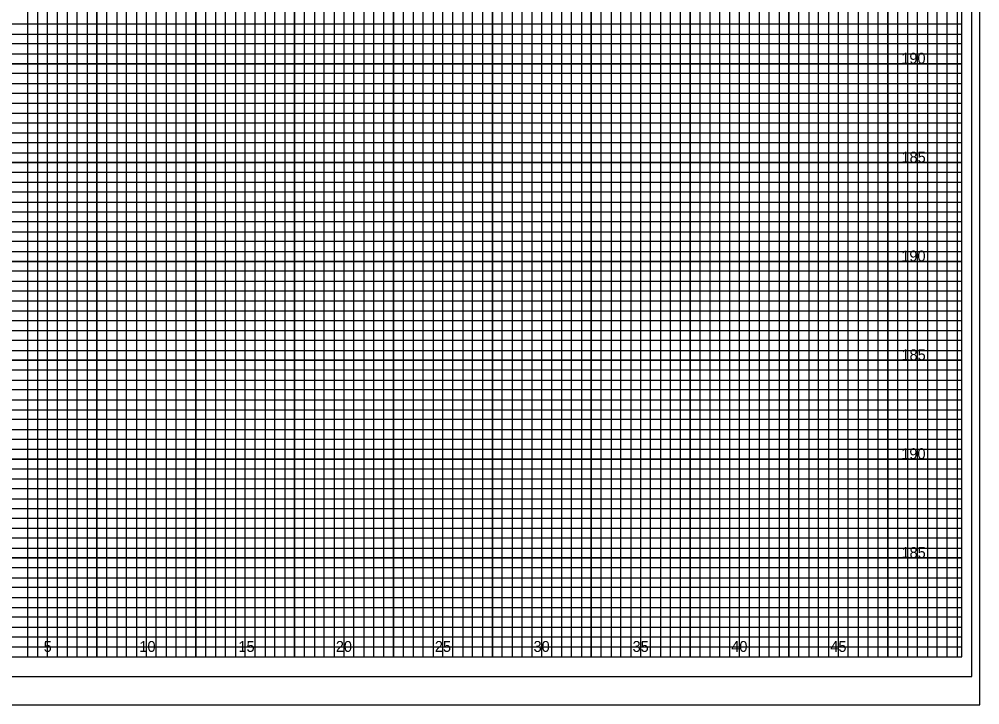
# Model space of a CAD drawing. Extents: x -4 to 103, y -2 to 138.
# Drawn here: x 54.82 to 103.4, y -2.43 to 32.25 of the extents above; entities that cross this region are included whole.
import ezdxf

# ---------------------------------------------------------------- set-up
doc = ezdxf.new("R2010")
doc.units = 0
for name, color, linetype in [('Old_Level_10', 7, 'Continuous'), ('Old_Level_16', 7, 'Continuous'), ('Old_Level_3', 7, 'Continuous'), ('Old_Level_4', 7, 'Continuous'), ('Old_Level_5', 7, 'Continuous'), ('Old_Level_8', 7, 'Continuous'), ('Prop Dimension', 7, 'Continuous'), ('Prop XS Finish Grade', 7, 'Continuous'), ('Prop XS SE Text', 7, 'Continuous')]:
    doc.layers.add(name, color=color, linetype=linetype)

msp = doc.modelspace()

# ---------------------------------------------------------------- linework, layer by layer
at = {"layer": 'Old_Level_10'}
for p, q in [((56.25, 0), (56.25, 65)), ((58.75, 0), (58.75, 65)), ((61.25, 0), (61.25, 65)), ((63.75, 0), (63.75, 65)), ((66.25, 0), (66.25, 65)), ((68.75, 0), (68.75, 65)), ((71.25, 0), (71.25, 65)), ((73.75, 0), (73.75, 65)), ((91.25, 0), (91.25, 63.425)), ((93.75, 0), (93.75, 63.425)), ((96.25, 0), (96.25, 63.425)), ((98.75, 0), (98.75, 63.425)), ((101.25, 0), (101.25, 63.425)), ((76.25, 0), (76.25, 62)), ((78.75, 0), (78.75, 62)), ((81.25, 0), (81.25, 62)), ((83.75, 0), (83.75, 62)), ((86.25, 0), (86.25, 62)), ((88.75, 0), (88.75, 62)), ((0, 30), (102.5, 30)), ((0, 27.5), (102.5, 27.5)), ((0, 25), (102.5, 25)), ((0, 22.5), (102.5, 22.5)), ((0, 20), (102.5, 20)), ((0, 17.5), (102.5, 17.5)), ((0, 15), (102.5, 15)), ((0, 12.5), (102.5, 12.5)), ((0, 10), (102.5, 10)), ((0, 7.5), (102.5, 7.5)), ((0, 5), (102.5, 5)), ((0, 2.5), (102.5, 2.5))]:
    msp.add_line(p, q, dxfattribs=at)
at = {"layer": 'Old_Level_3'}
msp.add_line((-3.5, -2.425), (102.1625, -2.425), dxfattribs=at)
at = {"layer": 'Old_Level_4'}
msp.add_lwpolyline([(103, 66), (-2.8, 66), (-2.8, -1), (103, -1)], close=True, dxfattribs=at)
at = {"layer": 'Old_Level_5'}
msp.add_lwpolyline([(103.4, 67.4), (-3.5, 67.4), (-3.5, -2.425), (103.4, -2.425)], close=True, dxfattribs=at)
at = {"layer": 'Old_Level_8'}
for points in [[(56.25, 0), (56.25, 65)], [(58.75, 65), (58.75, 0), (61.25, 0), (61.25, 65)], [(63.75, 65), (63.75, 0), (66.25, 0), (66.25, 65)], [(68.75, 65), (68.75, 0), (71.25, 0), (71.25, 65)], [(73.75, 65), (73.75, 0), (76.25, 0), (76.25, 62)], [(88.75, 62), (88.75, 0), (91.25, 0), (91.25, 63.425)], [(93.75, 63.425), (93.75, 0), (96.25, 0), (96.25, 63.425)], [(98.75, 63.425), (98.75, 0), (101.25, 0), (101.25, 63.425)], [(78.75, 62), (78.75, 0), (81.25, 0), (81.25, 62)], [(83.75, 62), (83.75, 0), (86.25, 0), (86.25, 62)], [(0, 27.5), (102.5, 27.5), (102.5, 30), (0, 30)], [(0, 22.5), (102.5, 22.5), (102.5, 25), (0, 25)], [(0, 17.5), (102.5, 17.5), (102.5, 20), (0, 20)], [(0, 12.5), (102.5, 12.5), (102.5, 15), (0, 15)], [(0, 7.5), (102.5, 7.5), (102.5, 10), (0, 10)], [(0, 2.5), (102.5, 2.5), (102.5, 5), (0, 5)]]:
    msp.add_lwpolyline(points, dxfattribs=at)
at = {"layer": 'Prop Dimension'}
for points in [[(54.75, 0), (55.25, 0), (55.25, 65)], [(55.75, 65), (55.75, 0), (56.75, 0), (56.75, 65)], [(57.25, 65), (57.25, 0), (57.75, 0), (57.75, 65)], [(58.25, 65), (58.25, 0), (59.25, 0), (59.25, 65)], [(59.75, 65), (59.75, 0), (60.25, 0), (60.25, 65)], [(60.75, 65), (60.75, 0), (61.75, 0), (61.75, 65)], [(62.25, 65), (62.25, 0), (62.75, 0), (62.75, 65)], [(63.25, 65), (63.25, 0), (64.25, 0), (64.25, 65)], [(64.75, 65), (64.75, 0), (65.25, 0), (65.25, 65)], [(65.75, 65), (65.75, 0), (66.75, 0), (66.75, 65)], [(67.25, 65), (67.25, 0), (67.75, 0), (67.75, 65)], [(68.25, 65), (68.25, 0), (69.25, 0), (69.25, 65)], [(69.75, 65), (69.75, 0), (70.25, 0), (70.25, 65)], [(70.75, 65), (70.75, 0), (71.75, 0), (71.75, 65)], [(72.25, 65), (72.25, 0), (72.75, 0), (72.75, 65)], [(73.25, 65), (73.25, 0), (74.25, 0), (74.25, 62)], [(89.75, 62), (89.75, 0), (90.25, 0), (90.25, 63.425)], [(90.75, 63.425), (90.75, 0), (91.75, 0), (91.75, 63.425)], [(92.25, 63.425), (92.25, 0), (92.75, 0), (92.75, 63.425)], [(93.25, 63.425), (93.25, 0), (94.25, 0), (94.25, 63.425)], [(94.75, 63.425), (94.75, 0), (95.25, 0), (95.25, 63.425)], [(95.75, 63.425), (95.75, 0), (96.75, 0), (96.75, 63.425)], [(97.25, 63.425), (97.25, 0), (97.75, 0), (97.75, 63.425)], [(98.25, 63.425), (98.25, 0), (99.25, 0), (99.25, 63.425)], [(99.75, 63.425), (99.75, 0), (100.25, 0), (100.25, 63.425)], [(100.25, 63.425), (100.75, 63.425), (100.75, 0), (101.75, 0), (101.75, 63.425), (102.25, 63.425), (102.25, 0)], [(74.75, 62), (74.75, 0), (75.25, 0), (75.25, 62)], [(75.75, 62), (75.75, 0), (76.75, 0), (76.75, 62)], [(77.25, 62), (77.25, 0), (77.75, 0), (77.75, 62)], [(78.25, 62), (78.25, 0), (79.25, 0), (79.25, 62)], [(79.75, 62), (79.75, 0), (80.25, 0), (80.25, 62)], [(80.75, 62), (80.75, 0), (81.75, 0), (81.75, 62)], [(82.25, 62), (82.25, 0), (82.75, 0), (82.75, 62)], [(83.25, 62), (83.25, 0), (84.25, 0), (84.25, 62)], [(84.75, 62), (84.75, 0), (85.25, 0), (85.25, 62)], [(85.75, 62), (85.75, 0), (86.75, 0), (86.75, 62)], [(87.25, 62), (87.25, 0), (87.75, 0), (87.75, 62)], [(88.25, 62), (88.25, 0), (89.25, 0), (89.25, 62)], [(0, 31.5), (102.5, 31.5), (102.5, 32), (0, 32)], [(0, 30.5), (102.5, 30.5), (102.5, 31), (0, 31)], [(0, 29), (102.5, 29), (102.5, 29.5), (0, 29.5)], [(0, 28), (102.5, 28), (102.5, 28.5), (0, 28.5)], [(0, 26.5), (102.5, 26.5), (102.5, 27), (0, 27)], [(0, 25.5), (102.5, 25.5), (102.5, 26), (0, 26)], [(0, 24), (102.5, 24), (102.5, 24.5), (0, 24.5)], [(0, 23), (102.5, 23), (102.5, 23.5), (0, 23.5)], [(0, 21.5), (102.5, 21.5), (102.5, 22), (0, 22)], [(0, 20.5), (102.5, 20.5), (102.5, 21), (0, 21)], [(0, 19), (102.5, 19), (102.5, 19.5), (0, 19.5)], [(0, 18), (102.5, 18), (102.5, 18.5), (0, 18.5)], [(0, 16.5), (102.5, 16.5), (102.5, 17), (0, 17)], [(0, 15.5), (102.5, 15.5), (102.5, 16), (0, 16)], [(0, 14), (102.5, 14), (102.5, 14.5), (0, 14.5)], [(0, 13), (102.5, 13), (102.5, 13.5), (0, 13.5)], [(0, 11.5), (102.5, 11.5), (102.5, 12), (0, 12)], [(0, 10.5), (102.5, 10.5), (102.5, 11), (0, 11)], [(0, 9), (102.5, 9), (102.5, 9.5), (0, 9.5)], [(0, 8), (102.5, 8), (102.5, 8.5), (0, 8.5)], [(0, 6.5), (102.5, 6.5), (102.5, 7), (0, 7)], [(0, 5.5), (102.5, 5.5), (102.5, 6), (0, 6)], [(0, 4), (102.5, 4), (102.5, 4.5), (0, 4.5)], [(0, 3), (102.5, 3), (102.5, 3.5), (0, 3.5)], [(0, 1.5), (102.5, 1.5), (102.5, 2), (0, 2)], [(0, 0.5), (102.5, 0.5), (102.5, 1), (0, 1)]]:
    msp.add_lwpolyline(points, dxfattribs=at)
at = {"layer": 'Prop XS SE Text'}
msp.add_line((-3.5, -2.425), (103.4, -2.425), dxfattribs=at)
msp.add_lwpolyline([(102.5, 65), (0, 65), (0, 0), (102.5, 0)], close=True, dxfattribs=at)

# ---------------------------------------------------------------- texts
at = {"layer": 'Old_Level_16'}
for s, p in [('5', (56.0574, 0.25)), ('10', (60.8971, 0.25)), ('15', (65.9057, 0.25)), ('20', (70.8312, 0.25)), ('25', (75.8399, 0.25)), ('30', (80.8312, 0.25)), ('35', (85.8399, 0.25)), ('40', (90.8313, 0.25)), ('45', (95.8399, 0.25))]:
    msp.add_text(s, height=0.55, dxfattribs=at).set_placement(p)
at = {"layer": 'Prop XS Finish Grade'}
for s, p in [('190', (99.4296, 30)), ('185', (99.4383, 25)), ('190', (99.4296, 20)), ('185', (99.4383, 15)), ('190', (99.4296, 10)), ('185', (99.4383, 5))]:
    msp.add_text(s, height=0.55, dxfattribs=at).set_placement(p)

doc.saveas('drawing.dxf')
